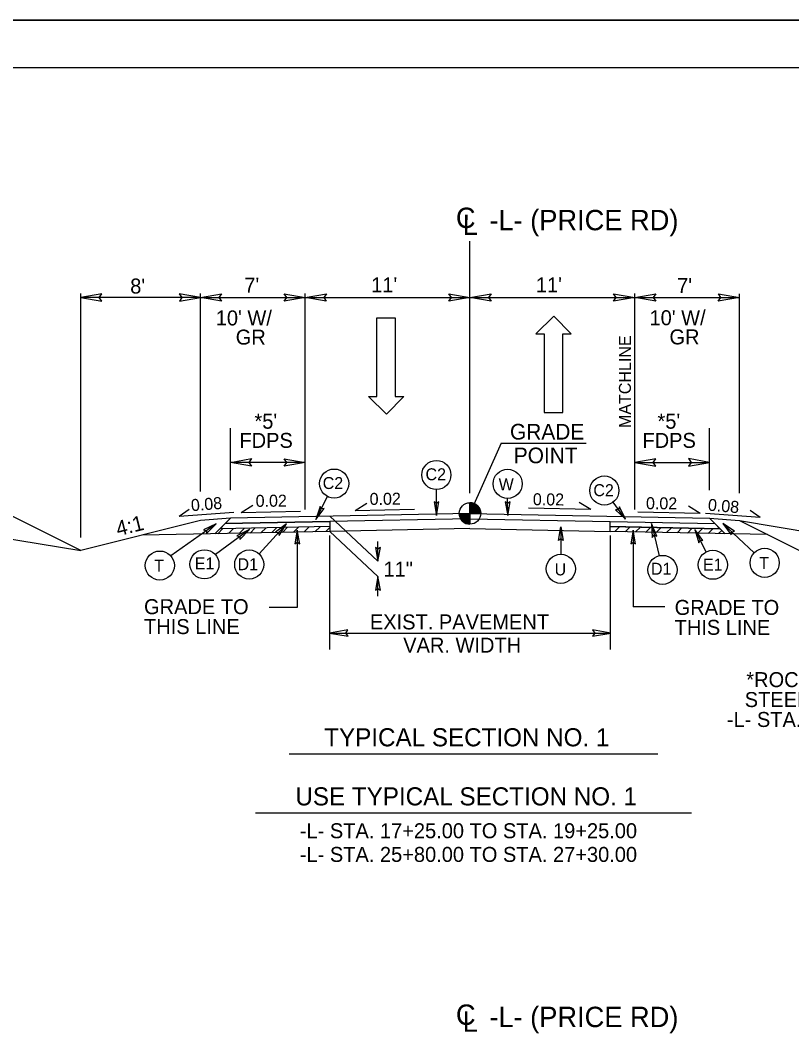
# Model space of a CAD drawing. Extents: x 1184121 to 1184397, y 1246506 to 1246661.
# Drawn here: x 1184197.8 to 1184249.3, y 1246592.7 to 1246660.5 of the extents above; entities that cross this region are included whole.
import ezdxf

# ---------------------------------------------------------------- set-up
doc = ezdxf.new("R2010")
doc.units = 0
for name, color, linetype in [('Prop Shade Light', 7, 'Continuous'), ('Sheet Data Field CELL', 7, 'Continuous'), ('Sheet Plan CELL', 7, 'Continuous'), ('Sheet Plot Border Outside CELL', 7, 'Continuous'), ('z - Construction', 7, 'Continuous')]:
    doc.layers.add(name, color=color, linetype=linetype)

msp = doc.modelspace()

# ---------------------------------------------------------------- linework, layer by layer
at = {"layer": 'Prop Shade Light'}
for points in [[(1184211.43, 1246626.925), (1184218.418, 1246627.065), (1184218.418, 1246626.735), (1184211.094, 1246626.588)], [(1184244.482, 1246626.588), (1184237.146, 1246626.735), (1184237.146, 1246627.065), (1184244.145, 1246626.925)]]:
    msp.add_lwpolyline(points, close=True, dxfattribs=at)
at = {"layer": 'Sheet Data Field CELL'}
for p, q in [((1184227.788, 1246628.968), (1184227.788, 1246645.774)), ((1184201.788, 1246625.998), (1184201.788, 1246642.289)), ((1184209.788, 1246629.079), (1184209.788, 1246642.289)), ((1184216.788, 1246627.864), (1184216.788, 1246642.289)), ((1184238.788, 1246627.864), (1184238.788, 1246642.289)), ((1184245.788, 1246628.968), (1184245.788, 1246642.273)), ((1184209.788, 1246642.024), (1184201.788, 1246642.025)), ((1184209.788, 1246642.024), (1184216.788, 1246642.024)), ((1184216.788, 1246642.024), (1184227.788, 1246642.024)), ((1184227.788, 1246642.024), (1184238.788, 1246642.024)), ((1184238.788, 1246642.024), (1184245.788, 1246642.024)), ((1184221.565, 1246635.41), (1184221.565, 1246640.66)), ((1184221.565, 1246640.66), (1184222.802, 1246640.66)), ((1184222.802, 1246640.66), (1184222.802, 1246635.41)), ((1184233.39, 1246640.782), (1184232.19, 1246639.601)), ((1184234.552, 1246639.601), (1184233.39, 1246640.782)), ((1184232.19, 1246639.601), (1184232.752, 1246639.601)), ((1184232.752, 1246639.601), (1184232.752, 1246634.351)), ((1184233.99, 1246634.351), (1184233.99, 1246639.601)), ((1184233.99, 1246639.601), (1184234.552, 1246639.601)), ((1184222.202, 1246634.229), (1184221.002, 1246635.41)), ((1184221.002, 1246635.41), (1184221.565, 1246635.41)), ((1184223.365, 1246635.41), (1184222.202, 1246634.229)), ((1184222.802, 1246635.41), (1184223.365, 1246635.41)), ((1184232.752, 1246634.351), (1184233.99, 1246634.351)), ((1184211.788, 1246629.155), (1184211.788, 1246633.294)), ((1184243.788, 1246629.155), (1184243.788, 1246633.294)), ((1184229.878, 1246632.291), (1184227.788, 1246627.603)), ((1184229.878, 1246632.291), (1184235.539, 1246632.291)), ((1184201.788, 1246625.123), (1184189.63, 1246631.202)), ((1184216.788, 1246631.013), (1184211.788, 1246631.013)), ((1184238.788, 1246631.013), (1184243.788, 1246631.013)), ((1184217.502, 1246627.19), (1184218.278, 1246628.73)), ((1184225.547, 1246627.476), (1184225.546, 1246629.2)), ((1184230.306, 1246627.465), (1184230.305, 1246628.613)), ((1184212.497, 1246627.678), (1184213.28, 1246628.152)), ((1184220.11, 1246627.808), (1184220.893, 1246628.281)), ((1184227.788, 1246627.603), (1184227.788, 1246628.319)), ((1184235.868, 1246627.864), (1184231.704, 1246627.947)), ((1184235.868, 1246627.864), (1184235.085, 1246628.337)), ((1184238.182, 1246627.213), (1184237.341, 1246628.352)), ((1184243.159, 1246627.608), (1184242.376, 1246628.081)), ((1184208.36, 1246627.425), (1184209.043, 1246627.896)), ((1184208.36, 1246627.425), (1184212.016, 1246627.697)), ((1184211.789, 1246627.283), (1184209.789, 1246627.123)), ((1184211.789, 1246627.283), (1184210.753, 1246626.248)), ((1184227.788, 1246627.603), (1184211.789, 1246627.283)), ((1184212.497, 1246627.678), (1184216.463, 1246627.758)), ((1184218.418, 1246627.416), (1184221.645, 1246624.416)), ((1184227.791, 1246627.252), (1184218.418, 1246627.065)), ((1184220.11, 1246627.808), (1184224.075, 1246627.887)), ((1184227.071, 1246627.603), (1184227.788, 1246627.603)), ((1184227.786, 1246626.887), (1184227.788, 1246627.603)), ((1184227.788, 1246627.603), (1184227.786, 1246626.887)), ((1184228.504, 1246627.603), (1184227.788, 1246627.603)), ((1184227.788, 1246627.603), (1184243.787, 1246627.283)), ((1184227.788, 1246627.252), (1184237.146, 1246627.065)), ((1184243.159, 1246627.608), (1184238.994, 1246627.691)), ((1184247.174, 1246627.331), (1184243.518, 1246627.604)), ((1184243.786, 1246627.283), (1184244.822, 1246626.248)), ((1184243.786, 1246627.283), (1184245.787, 1246627.123)), ((1184247.174, 1246627.331), (1184246.491, 1246627.802)), ((1184189.63, 1246627.149), (1184201.788, 1246625.123)), ((1184209.789, 1246627.123), (1184201.788, 1246625.123)), ((1184210.84, 1246626.914), (1184207.803, 1246624.77)), ((1184210.941, 1246626.252), (1184211.281, 1246626.592)), ((1184218.418, 1246626.735), (1184211.094, 1246626.588)), ((1184218.418, 1246627.065), (1184211.43, 1246626.925)), ((1184211.662, 1246626.266), (1184212.003, 1246626.606)), ((1184212.384, 1246626.281), (1184212.724, 1246626.621)), ((1184213.106, 1246626.295), (1184213.446, 1246626.635)), ((1184215.545, 1246626.906), (1184213.702, 1246624.911)), ((1184213.827, 1246626.309), (1184214.167, 1246626.65)), ((1184214.549, 1246626.324), (1184214.889, 1246626.664)), ((1184215.27, 1246626.338), (1184215.61, 1246626.678)), ((1184215.992, 1246626.353), (1184216.332, 1246626.693)), ((1184216.713, 1246626.367), (1184217.053, 1246626.707)), ((1184217.435, 1246626.382), (1184217.775, 1246626.722)), ((1184218.156, 1246626.396), (1184218.418, 1246626.657)), ((1184218.418, 1246627.065), (1184218.418, 1246626.401)), ((1184227.788, 1246626.589), (1184218.418, 1246626.401)), ((1184227.788, 1246626.589), (1184237.146, 1246626.401)), ((1184233.854, 1246626.707), (1184233.853, 1246624.878)), ((1184237.139, 1246626.735), (1184244.482, 1246626.588)), ((1184237.146, 1246626.401), (1184237.146, 1246627.065)), ((1184237.146, 1246627.065), (1184244.145, 1246626.925)), ((1184237.459, 1246626.395), (1184237.786, 1246626.722)), ((1184238.152, 1246626.381), (1184238.479, 1246626.708)), ((1184238.845, 1246626.367), (1184239.172, 1246626.694)), ((1184239.538, 1246626.353), (1184239.865, 1246626.68)), ((1184239.907, 1246626.925), (1184240.421, 1246624.781)), ((1184240.232, 1246626.34), (1184240.559, 1246626.667)), ((1184240.925, 1246626.326), (1184241.252, 1246626.653)), ((1184241.618, 1246626.312), (1184241.945, 1246626.639)), ((1184242.311, 1246626.298), (1184242.638, 1246626.625)), ((1184243.005, 1246626.284), (1184243.332, 1246626.611)), ((1184243.698, 1246626.27), (1184244.025, 1246626.597)), ((1184244.678, 1246626.928), (1184246.77, 1246624.979)), ((1184245.788, 1246627.123), (1184261.307, 1246624.537)), ((1184245.788, 1246627.123), (1184261.307, 1246619.364)), ((1184218.418, 1246626.401), (1184205.899, 1246626.151)), ((1184213.055, 1246626.534), (1184210.782, 1246624.853)), ((1184216.257, 1246626.48), (1184216.257, 1246621.33)), ((1184218.416, 1246626.131), (1184218.416, 1246618.52)), ((1184218.418, 1246626.401), (1184221.645, 1246623.401)), ((1184247.652, 1246626.191), (1184237.146, 1246626.401)), ((1184237.154, 1246626.131), (1184237.154, 1246618.52)), ((1184238.686, 1246626.492), (1184238.686, 1246621.359)), ((1184242.805, 1246626.538), (1184243.551, 1246625.035)), ((1184244.391, 1246626.256), (1184244.601, 1246626.466)), ((1184221.645, 1246624.416), (1184221.645, 1246625.721)), ((1184221.645, 1246622.085), (1184221.645, 1246623.401)), ((1184216.257, 1246621.33), (1184214.379, 1246621.33)), ((1184240.804, 1246621.359), (1184238.686, 1246621.359)), ((1184218.416, 1246619.619), (1184237.154, 1246619.619)), ((1184215.705, 1246611.558), (1184240.342, 1246611.558)), ((1184213.463, 1246607.614), (1184242.584, 1246607.614))]:
    msp.add_line(p, q, dxfattribs=at)
for points in [[(1184203.194, 1246642.267), (1184201.788, 1246642.025), (1184203.201, 1246641.775), (1184203.022, 1246642.025)], [(1184208.382, 1246641.782), (1184209.788, 1246642.024), (1184208.374, 1246642.274), (1184208.553, 1246642.024)], [(1184211.194, 1246641.782), (1184209.788, 1246642.024), (1184211.201, 1246642.274), (1184211.022, 1246642.024)], [(1184215.382, 1246642.267), (1184216.788, 1246642.024), (1184215.374, 1246641.774), (1184215.554, 1246642.024)], [(1184218.194, 1246641.782), (1184216.788, 1246642.024), (1184218.202, 1246642.274), (1184218.022, 1246642.024)], [(1184226.382, 1246642.267), (1184227.788, 1246642.024), (1184226.374, 1246641.774), (1184226.554, 1246642.024)], [(1184229.194, 1246641.782), (1184227.788, 1246642.024), (1184229.202, 1246642.274), (1184229.022, 1246642.024)], [(1184237.382, 1246642.266), (1184238.788, 1246642.024), (1184237.374, 1246641.774), (1184237.554, 1246642.024)], [(1184240.194, 1246641.782), (1184238.788, 1246642.024), (1184240.202, 1246642.274), (1184240.022, 1246642.024)], [(1184244.382, 1246642.266), (1184245.788, 1246642.024), (1184244.374, 1246641.774), (1184244.554, 1246642.024)], [(1184213.194, 1246630.77), (1184211.788, 1246631.013), (1184213.201, 1246631.263), (1184213.022, 1246631.013)], [(1184215.382, 1246631.255), (1184216.788, 1246631.013), (1184215.374, 1246630.763), (1184215.553, 1246631.013)], [(1184240.194, 1246631.255), (1184238.788, 1246631.013), (1184240.202, 1246630.763), (1184240.022, 1246631.013)], [(1184242.382, 1246630.77), (1184243.788, 1246631.013), (1184242.374, 1246631.263), (1184242.554, 1246631.013)], [(1184217.772, 1246628.073), (1184217.502, 1246627.19), (1184218.058, 1246627.934), (1184217.861, 1246627.903)], [(1184225.39, 1246628.385), (1184225.547, 1246627.476), (1184225.708, 1246628.39), (1184225.547, 1246628.274)], [(1184230.148, 1246628.375), (1184230.306, 1246627.465), (1184230.467, 1246628.38), (1184230.305, 1246628.264)], [(1184237.516, 1246627.852), (1184238.182, 1246627.213), (1184237.769, 1246628.045), (1184237.708, 1246627.855)], [(1184210.188, 1246626.262), (1184210.84, 1246626.914), (1184210, 1246626.519), (1184210.188, 1246626.454)], [(1184215.043, 1246626.132), (1184215.545, 1246626.906), (1184214.806, 1246626.344), (1184215.004, 1246626.32)], [(1184233.697, 1246625.797), (1184233.854, 1246626.707), (1184234.016, 1246625.792), (1184233.854, 1246625.909)], [(1184240.271, 1246626.077), (1184239.907, 1246626.925), (1184239.963, 1246625.998), (1184240.093, 1246626.149)], [(1184245.45, 1246626.423), (1184244.678, 1246626.928), (1184245.237, 1246626.187), (1184245.262, 1246626.384)], [(1184212.417, 1246625.867), (1184213.055, 1246626.534), (1184212.223, 1246626.12), (1184212.413, 1246626.059)], [(1184216.414, 1246625.57), (1184216.257, 1246626.48), (1184216.095, 1246625.565), (1184216.257, 1246625.681)], [(1184238.843, 1246625.583), (1184238.686, 1246626.492), (1184238.524, 1246625.578), (1184238.686, 1246625.694)], [(1184243.35, 1246625.793), (1184242.805, 1246626.538), (1184243.067, 1246625.647), (1184243.16, 1246625.823)], [(1184221.488, 1246625.325), (1184221.645, 1246624.416), (1184221.806, 1246625.331), (1184221.645, 1246625.214)], [(1184221.802, 1246622.491), (1184221.645, 1246623.401), (1184221.483, 1246622.486), (1184221.645, 1246622.603)], [(1184219.641, 1246619.83), (1184218.416, 1246619.619), (1184219.648, 1246619.401), (1184219.491, 1246619.619)], [(1184235.982, 1246619.408), (1184237.207, 1246619.619), (1184235.975, 1246619.837), (1184236.132, 1246619.619)]]:
    msp.add_lwpolyline(points, close=True, dxfattribs=at)
for points in [[(1184227.794, 1246628.319), (1184227.794, 1246628.319), (1184227.794, 1246627.603)], [(1184227.808, 1246628.319), (1184227.808, 1246627.603)], [(1184227.823, 1246628.318), (1184227.823, 1246627.603)], [(1184227.837, 1246628.318), (1184227.837, 1246627.603)], [(1184227.851, 1246628.316), (1184227.851, 1246627.603)], [(1184227.866, 1246628.315), (1184227.866, 1246627.603)], [(1184227.88, 1246628.313), (1184227.88, 1246627.603)], [(1184227.894, 1246628.311), (1184227.894, 1246627.603)], [(1184227.909, 1246628.31), (1184227.909, 1246627.603)], [(1184227.923, 1246628.307), (1184227.923, 1246627.603)], [(1184227.937, 1246628.303), (1184227.937, 1246627.603)], [(1184227.952, 1246628.3), (1184227.952, 1246627.603)], [(1184227.966, 1246628.297), (1184227.966, 1246627.603)], [(1184227.98, 1246628.292), (1184227.98, 1246627.603)], [(1184227.995, 1246628.289), (1184227.995, 1246627.603)], [(1184228.009, 1246628.284), (1184228.009, 1246627.603)], [(1184228.023, 1246628.28), (1184228.023, 1246627.603)], [(1184228.038, 1246628.275), (1184228.038, 1246627.603)], [(1184228.052, 1246628.268), (1184228.052, 1246627.603)], [(1184228.066, 1246628.262), (1184228.066, 1246627.603)], [(1184228.08, 1246628.256), (1184228.08, 1246627.603)], [(1184228.095, 1246628.249), (1184228.095, 1246627.603)], [(1184228.109, 1246628.243), (1184228.109, 1246627.603)], [(1184228.123, 1246628.235), (1184228.123, 1246627.603)], [(1184228.138, 1246628.227), (1184228.138, 1246627.603)], [(1184228.152, 1246628.219), (1184228.152, 1246627.603)], [(1184228.166, 1246628.211), (1184228.166, 1246627.603)], [(1184228.181, 1246628.202), (1184228.181, 1246627.603)], [(1184228.195, 1246628.192), (1184228.195, 1246627.603)], [(1184228.209, 1246628.181), (1184228.209, 1246627.603)], [(1184228.224, 1246628.171), (1184228.224, 1246627.603)], [(1184228.238, 1246628.16), (1184228.238, 1246627.603)], [(1184228.252, 1246628.148), (1184228.252, 1246627.603)], [(1184228.267, 1246628.135), (1184228.267, 1246627.603)], [(1184228.281, 1246628.122), (1184228.281, 1246627.603)], [(1184228.295, 1246628.108), (1184228.295, 1246627.603)], [(1184228.31, 1246628.093), (1184228.31, 1246627.603)], [(1184228.324, 1246628.077), (1184228.324, 1246627.603)], [(1184228.338, 1246628.06), (1184228.338, 1246627.603)], [(1184228.353, 1246628.042), (1184228.353, 1246627.603)], [(1184228.367, 1246628.023), (1184228.367, 1246627.603)], [(1184228.381, 1246628.003), (1184228.381, 1246627.603)], [(1184228.396, 1246627.98), (1184228.396, 1246627.603)], [(1184228.41, 1246627.957), (1184228.41, 1246627.603)], [(1184228.424, 1246627.931), (1184228.424, 1246627.603)], [(1184227.075, 1246627.603), (1184227.075, 1246627.525)], [(1184227.089, 1246627.603), (1184227.089, 1246627.441)], [(1184227.103, 1246627.603), (1184227.103, 1246627.39)], [(1184227.118, 1246627.603), (1184227.118, 1246627.347)], [(1184227.132, 1246627.603), (1184227.132, 1246627.314)], [(1184227.146, 1246627.603), (1184227.146, 1246627.283)], [(1184227.161, 1246627.603), (1184227.161, 1246627.256)], [(1184227.175, 1246627.603), (1184227.175, 1246627.231)], [(1184227.189, 1246627.603), (1184227.189, 1246627.209)], [(1184227.204, 1246627.603), (1184227.204, 1246627.188)], [(1184227.218, 1246627.603), (1184227.218, 1246627.169)], [(1184227.232, 1246627.603), (1184227.232, 1246627.151)], [(1184227.247, 1246627.603), (1184227.247, 1246627.134)], [(1184227.261, 1246627.603), (1184227.261, 1246627.118)], [(1184227.275, 1246627.603), (1184227.275, 1246627.102)], [(1184227.29, 1246627.603), (1184227.29, 1246627.088)], [(1184227.304, 1246627.603), (1184227.304, 1246627.075)], [(1184227.318, 1246627.603), (1184227.318, 1246627.062)], [(1184227.333, 1246627.603), (1184227.333, 1246627.049)], [(1184227.347, 1246627.603), (1184227.347, 1246627.038)], [(1184227.361, 1246627.603), (1184227.361, 1246627.027)], [(1184227.375, 1246627.603), (1184227.375, 1246627.018)], [(1184227.39, 1246627.603), (1184227.39, 1246627.008)], [(1184227.404, 1246627.603), (1184227.404, 1246626.998)], [(1184227.418, 1246627.603), (1184227.418, 1246626.989)], [(1184227.433, 1246627.603), (1184227.433, 1246626.981)], [(1184227.447, 1246627.603), (1184227.447, 1246626.973)], [(1184227.461, 1246627.603), (1184227.461, 1246626.965)], [(1184227.476, 1246627.603), (1184227.476, 1246626.959)], [(1184227.49, 1246627.603), (1184227.49, 1246626.952)], [(1184227.504, 1246627.603), (1184227.504, 1246626.946)], [(1184227.519, 1246627.603), (1184227.519, 1246626.94)], [(1184227.533, 1246627.603), (1184227.533, 1246626.933)], [(1184227.547, 1246627.603), (1184227.547, 1246626.928)], [(1184227.562, 1246627.603), (1184227.562, 1246626.924)], [(1184227.576, 1246627.603), (1184227.576, 1246626.919)], [(1184227.59, 1246627.603), (1184227.59, 1246626.916)], [(1184227.605, 1246627.603), (1184227.605, 1246626.911)], [(1184227.619, 1246627.603), (1184227.619, 1246626.908)], [(1184227.633, 1246627.603), (1184227.633, 1246626.905)], [(1184227.648, 1246627.603), (1184227.648, 1246626.901)], [(1184227.662, 1246627.603), (1184227.662, 1246626.898)], [(1184227.676, 1246627.603), (1184227.676, 1246626.897)], [(1184227.691, 1246627.603), (1184227.691, 1246626.893)], [(1184227.705, 1246627.603), (1184227.705, 1246626.892)], [(1184227.719, 1246627.603), (1184227.719, 1246626.89)], [(1184227.734, 1246627.603), (1184227.734, 1246626.889)], [(1184227.748, 1246627.603), (1184227.748, 1246626.889)], [(1184227.762, 1246627.603), (1184227.762, 1246626.887)], [(1184227.777, 1246627.603), (1184227.777, 1246626.887), (1184227.777, 1246626.887)], [(1184228.439, 1246627.901), (1184228.439, 1246627.603)], [(1184228.453, 1246627.867), (1184228.453, 1246627.603)], [(1184228.467, 1246627.828), (1184228.467, 1246627.603)], [(1184228.482, 1246627.778), (1184228.482, 1246627.603)], [(1184228.496, 1246627.705), (1184228.496, 1246627.603)]]:
    msp.add_lwpolyline(points, dxfattribs=at)
for centre, radius in [((1184225.546, 1246630.172), 0.972), ((1184218.716, 1246629.598), 0.972), ((1184230.305, 1246629.585), 0.972), ((1184236.764, 1246629.134), 0.972), ((1184227.787, 1246627.603), 0.716), ((1184247.474, 1246624.309), 0.972), ((1184207.076, 1246624.125), 0.972), ((1184210.052, 1246624.211), 0.972), ((1184213.046, 1246624.193), 0.972), ((1184233.854, 1246623.905), 0.972), ((1184240.65, 1246623.836), 0.972), ((1184244.011, 1246624.179), 0.972)]:
    msp.add_circle(centre, radius, dxfattribs=at)
for start, end in [(359.99048, 89.99048), (179.99048, 269.99048)]:
    msp.add_arc((1184227.787, 1246627.603), 0.716, start, end, dxfattribs=at)
at = {"layer": 'Sheet Plan CELL'}
msp.add_line((1184358.423, 1246657.364), (1184126.184, 1246657.364), dxfattribs=at)
at = {"layer": 'Sheet Plot Border Outside CELL'}
msp.add_lwpolyline([(1184121.05, 1246660.53), (1184360.324, 1246660.53), (1184360.324, 1246505.708), (1184121.05, 1246505.708)], close=True, dxfattribs=at)
at = {"layer": 'z - Construction'}
msp.add_line((1184360.324, 1246660.53), (1184121.05, 1246660.53), dxfattribs=at)

# ---------------------------------------------------------------- texts
at = {"layer": 'Sheet Data Field CELL'}
for s, height, p in [('C', 1.36, (1184226.85, 1246646.662)), ('-L- (PRICE RD)', 1.36, (1184229.082, 1246646.513)), ('GRADE', 1.044, (1184230.46, 1246632.54)), ('POINT', 1.044, (1184230.712, 1246630.958)), ('C2', 0.8, (1184217.953, 1246629.235)), ('C2', 0.8, (1184224.818, 1246629.819)), ('W', 0.8, (1184229.702, 1246629.151)), ('C2', 0.8, (1184236.029, 1246628.758)), ('E1', 0.8, (1184209.404, 1246623.865)), ('D1', 0.8, (1184212.263, 1246623.816)), ('E1', 0.8, (1184243.353, 1246623.793)), ('U', 0.8, (1184233.441, 1246623.468)), ('D1', 0.8, (1184239.878, 1246623.51)), ('GRADE TO', 1, (1184206.019, 1246620.88)), ('GRADE TO ', 1, (1184241.458, 1246620.83)), ('THIS LINE', 1, (1184206.019, 1246619.55)), ('EXIST. PAVEMENT', 1, (1184221.105, 1246619.862)), ('THIS LINE', 1, (1184241.458, 1246619.5)), ('VAR. WIDTH', 1, (1184223.33, 1246618.313)), ('TYPICAL SECTION NO. 1', 1.20892, (1184218.055, 1246612.055)), ('USE TYPICAL SECTION NO. 1', 1.20892, (1184216.127, 1246608.111)), ('C', 1.36, (1184226.85, 1246593.459)), ('-L- (PRICE RD)', 1.36, (1184229.081, 1246593.309))]:
    msp.add_text(s, height=height, dxfattribs=at).set_placement(p)
for s, height, rotation, p in [('L', 1.361, 359.9469, (1184227.303, 1246646.198)), ("8'", 1, 359.99977, (1184205.096, 1246642.288)), ("7'", 1, 359.99977, (1184212.715, 1246642.349)), ("11'", 1, 359.99977, (1184221.188, 1246642.365)), ("11'", 1, 359.99977, (1184232.188, 1246642.365)), ("7'", 1, 359.99977, (1184241.621, 1246642.316)), ("10' W/", 1, 359.99977, (1184210.81, 1246640.158)), ("10' W/", 1, 359.99977, (1184239.779, 1246640.173)), ('GR', 1, 359.99977, (1184212.143, 1246638.878)), ('GR', 1, 359.99977, (1184241.112, 1246638.893)), ('MATCHLINE', 0.8, 90, (1184238.538, 1246633.309)), ("*5' ", 1, 359.99977, (1184213.394, 1246633.263)), ("*5' ", 1, 359.99977, (1184240.312, 1246633.263)), ('FDPS', 1, 359.99977, (1184212.39, 1246631.983)), ('FDPS', 1, 359.99977, (1184239.308, 1246631.983)), ('0.08', 0.8, 4.5736, (1184209.185, 1246627.751)), ('0.02', 0.8, 0.54024, (1184213.478, 1246628.042)), ('0.02', 0.8, 0.54024, (1184221.09, 1246628.172)), ('0.02', 0.8, 359.45976, (1184231.986, 1246628.154)), ('0.02', 0.8, 359.45976, (1184239.542, 1246627.893)), ('0.08', 0.8, 355.20917, (1184243.656, 1246627.795)), ('4:1', 1, 14.03605, (1184204.284, 1246626.08)), ('T', 0.8, 359.99971, (1184247.105, 1246623.901)), ('T', 0.8, 359.99971, (1184206.696, 1246623.724)), ('11"', 1, 359.99977, (1184222.012, 1246623.387)), ('*ROCK PLATE FILL SLOPE', 1, 360, (1184246.245, 1246616.008)), ('STEEPER THAN 2:1 FROM', 1, 360, (1184246.139, 1246614.678)), ('-L- STA. 17+45 TO 17+75 RT', 1, 360, (1184244.948, 1246613.348)), ('-L- STA. 17+25.00 TO STA. 19+25.00', 1, 0.00023, (1184216.426, 1246605.92)), ('-L- STA. 25+80.00 TO STA. 27+30.00', 1, 0.00023, (1184216.426, 1246604.339)), ('L', 1.361, 359.9469, (1184227.302, 1246592.995))]:
    msp.add_text(s, height=height, rotation=rotation, dxfattribs=at).set_placement(p)

doc.saveas('drawing.dxf')
